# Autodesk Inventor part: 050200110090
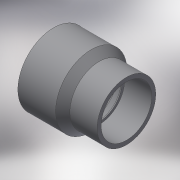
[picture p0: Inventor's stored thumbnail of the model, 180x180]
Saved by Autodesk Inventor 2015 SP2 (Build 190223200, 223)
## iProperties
Created: 2017-10
Part Number: 050200110090
Material: Generic
Description: PLASSON REDUCING SOCKET M.F.110(90)90 CEMENTED
Document SubType Name: Modeling
Designer: KIM
Density: 1 g/cm^3
Appearance: Default
Author: KIM
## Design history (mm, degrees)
derived "050200.ipt"
feature "Solid1::050200.ipt"
tag "TaggingFeature1"
body "Solid1"
other parameters: "d0" = 138, "d1" = 61, "d2" = 51, "d3" = 51, "d5" = 106, "d8" = 81, "d9" = 45 deg, "d12" = 0.9, "L_" = 61, "l_" = 51, "l_1" = 51, "E_" = 106, "H_" = 138, "d11" = 0.76772
